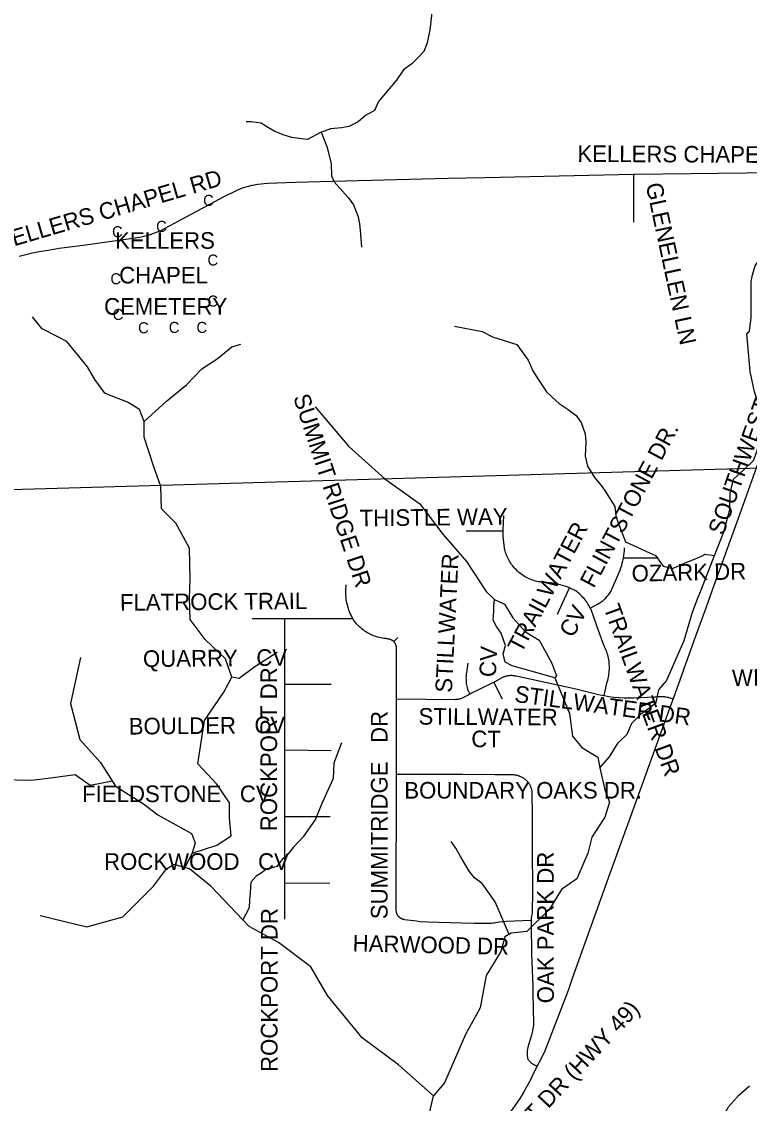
# Model space of a CAD drawing. Extents: x 1670563 to 1761545, y 515755 to 578944.
# Drawn here: x 1684631 to 1687923, y 530609 to 535500 of the extents above; entities that cross this region are included whole.
import ezdxf

# ---------------------------------------------------------------- set-up
doc = ezdxf.new("R2010")
doc.units = 0
for name, color, linetype in [('4_TwnRge', 7, 'Continuous'), ('CEMETERY', 7, 'Continuous'), ('Cross', 7, 'Continuous'), ('SHP_LINE', 7, 'Continuous'), ('STREETCL', 7, 'Continuous'), ('STRNAMES', 7, 'Continuous')]:
    doc.layers.add(name, color=color, linetype=linetype)

msp = doc.modelspace()

# ---------------------------------------------------------------- linework, layer by layer
at = {"layer": '4_TwnRge'}
msp.add_lwpolyline([(1677728, 533231.8), (1683031.7, 533346.7), (1683119.4, 533342.5), (1688238.5, 533490), (1688376.1, 533487.8), (1693684.6, 533590.9), (1698873.3, 533608.2), (1704126.3, 533645.6)], dxfattribs=at)
at = {"layer": 'SHP_LINE'}
for points in [[(1686501, 535615), (1686490, 535580), (1686486, 535528), (1686478, 535463), (1686465, 535405), (1686450, 535365), (1686421, 535334), (1686396, 535309), (1686359, 535282), (1686327, 535236), (1686246, 535139), (1686227, 535099), (1686187, 535076), (1686154, 535047), (1686112, 535026), (1686079, 535020), (1686029, 535016), (1685997, 535003), (1685987, 535001)], [(1685987, 535001), (1685924, 534968), (1685899, 534970), (1685853, 534976), (1685814, 534989), (1685774, 535005), (1685740, 535024), (1685715, 535041), (1685670, 535047), (1685647, 535047)], [(1685987, 535001), (1686012, 534936), (1686031, 534859), (1686033, 534803), (1686045, 534776), (1686108, 534705), (1686133, 534672), (1686154, 534617), (1686160, 534586), (1686162, 534557), (1686168, 534480)], [(1687766, 533086), (1687808, 533194), (1687834, 533294), (1687837, 533367), (1687851, 533432), (1687897, 533473), (1687942, 533516), (1687958, 533559), (1687975, 533638), (1687975, 533705), (1687969, 533759), (1687947, 533827), (1687926, 533919), (1687912, 534090), (1687923, 534101), (1687931, 534163), (1687931, 534176), (1687931, 534233), (1687931, 534266), (1687931, 534325), (1687937, 534355), (1687950, 534396), (1687958, 534409)], [(1685186, 533693), (1685164, 533747), (1685111, 533780), (1685037, 533808), (1685008, 533821), (1684963, 533882), (1684930, 533940), (1684877, 534005), (1684836, 534054), (1684795, 534075), (1684725, 534111), (1684705, 534136), (1684680, 534165)], [(1686589, 534123), (1686714, 534100), (1686762, 534075), (1686871, 534040), (1686922, 533969), (1686944, 533921), (1686970, 533880), (1687005, 533826), (1687031, 533803), (1687063, 533774), (1687104, 533746), (1687139, 533720), (1687162, 533688), (1687181, 533637), (1687184, 533599), (1687181, 533535), (1687191, 533490), (1687223, 533439), (1687255, 533401), (1687271, 533378), (1687315, 533308), (1687319, 533266), (1687328, 533238), (1687363, 533148), (1687472, 533099), (1687498, 533086), (1687533, 533038), (1687574, 533028), (1687594, 533035), (1687632, 533054), (1687683, 533073), (1687712, 533086), (1687722, 533092), (1687766, 533086)], [(1685186, 533693), (1685287, 533784), (1685377, 533858), (1685447, 533931), (1685516, 533976), (1685582, 534030), (1685623, 534042)], [(1685959, 533758), (1686112, 533579), (1686274, 533433), (1686433, 533320), (1686537, 533183), (1686644, 533060), (1686732, 532924), (1686771, 532888)], [(1685582, 532536), (1685553, 532619), (1685462, 532707), (1685394, 532797), (1685391, 532895), (1685394, 532979), (1685391, 533119), (1685329, 533232), (1685264, 533297), (1685261, 533398), (1685229, 533488), (1685186, 533621), (1685186, 533693)], [(1687246, 532127), (1687290, 532176), (1687329, 532239), (1687370, 532279), (1687392, 532328), (1687436, 532373), (1687473, 532400), (1687501, 532422), (1687514, 532479), (1687548, 532520), (1687628, 532702), (1687666, 532830), (1687692, 532898), (1687707, 532934), (1687766, 533086)], [(1686771, 532888), (1686816, 532867), (1686853, 532805), (1686910, 532742), (1686973, 532704), (1687028, 532603), (1687050, 532542), (1687043, 532534), (1686850, 532587), (1686818, 532604), (1686810, 532642), (1686820, 532679), (1686801, 532735), (1686780, 532766), (1686764, 532794), (1686767, 532836), (1686767, 532861), (1686771, 532888)], [(1685787, 532648), (1685686, 532583), (1685615, 532531), (1685582, 532536)], [(1684897, 532625), (1684852, 532417), (1684894, 532255), (1684988, 532151), (1685056, 532044), (1685183, 531963), (1685248, 531914), (1685400, 531830), (1685416, 531787), (1685403, 531741), (1685369, 531676)], [(1685403, 531741), (1685514, 531777), (1685579, 531819), (1685572, 531900), (1685572, 531968), (1685514, 532053), (1685429, 532144), (1685459, 532341), (1685546, 532468), (1685582, 532536)], [(1687043, 532534), (1687109, 532372), (1687123, 532270), (1687165, 532219), (1687237, 532175), (1687246, 532127)], [(1686078, 532239), (1686044, 532147), (1686040, 532079), (1685989, 531966), (1685960, 531894), (1685905, 531814), (1685887, 531795), (1685859, 531766), (1685830, 531729), (1685810, 531712), (1685786, 531680), (1685744, 531669), (1685734, 531665), (1685715, 531651), (1685692, 531636), (1685670, 531611), (1685667, 531596), (1685667, 531587), (1685665, 531561), (1685662, 531529), (1685661, 531493), (1685632, 531439)], [(1687246, 532127), (1687270, 532027), (1687290, 531971), (1687269, 531904), (1687211, 531813), (1687193, 531740), (1687143, 531624), (1687074, 531576), (1687019, 531487), (1686917, 531387), (1686846, 531379)], [(1685042, 532066), (1684942, 532046), (1684874, 532095), (1684774, 532082), (1684676, 532069), (1684540, 532072), (1684443, 532059), (1684355, 532053), (1684257, 531955), (1684173, 531897), (1684102, 531800)], [(1686836, 531373), (1686773, 531520), (1686714, 531604), (1686680, 531629), (1686655, 531659), (1686617, 531726), (1686596, 531764), (1686575, 531793)], [(1684715, 531459), (1684926, 531407), (1685089, 531453), (1685228, 531592), (1685287, 531670), (1685320, 531689)], [(1685632, 531439), (1685488, 531592), (1685391, 531670), (1685320, 531689)], [(1686495, 530643), (1686336, 530783), (1686171, 530906), (1686015, 531097), (1685940, 531227), (1685794, 531337), (1685661, 531409), (1685632, 531439)], [(1686846, 531379), (1686817, 531362), (1686799, 531296), (1686733, 531187), (1686706, 531041), (1686639, 530921), (1686544, 530703), (1686495, 530643)], [(1686476, 530565), (1686495, 530643)], [(1688266, 529793), (1687440, 530142), (1687363, 530202), (1687363, 530262), (1687401, 530294), (1687446, 530332), (1687455, 530395), (1687478, 530414), (1687573, 530455), (1687636, 530468), (1687712, 530468), (1687750, 530493), (1687788, 530531), (1687813, 530566), (1687829, 530594), (1687874, 530645), (1687924, 530689)]]:
    msp.add_lwpolyline(points, dxfattribs=at)
at = {"layer": 'STREETCL'}
for points in [[(1684619.7, 534440.2), (1684650.8, 534447.6), (1684681.1, 534454.3), (1684711.5, 534460.2), (1684752.2, 534467.6), (1684801.8, 534475.3), (1684873.6, 534484.6), (1684943.2, 534494.2), (1685166.7, 534526.4), (1685208.1, 534536), (1685234, 534545.7), (1685260.7, 534556), (1685544.2, 534707.6), (1685609.3, 534740.2), (1685630, 534748.3), (1685674.4, 534760.3), (1685700.3, 534765.4), (1685744, 534769.9), (1685869.8, 534775.1), (1686037.8, 534779.5), (1686560.8, 534792.1), (1686725.9, 534795.8), (1687398.8, 534810.5)], [(1687398.8, 534810.5), (1687405.4, 534810.6), (1687909.4, 534817.3), (1688089.3, 534821), (1688446, 534826.6)], [(1687398.8, 534810.5), (1687398.8, 534593.3)], [(1688443.6, 534819.6), (1688398.8, 534697.6), (1688346, 534561.1), (1688303.2, 534451.7), (1688196.4, 534149.1), (1688085.6, 533847.5), (1687978.7, 533549.9), (1687871.9, 533253.3), (1687762.2, 532951.2), (1687727.1, 532852.3), (1687671.8, 532700.8), (1687577.9, 532437.9)], [(1687109.5, 532940.2), (1687099.2, 532944.3), (1687088.7, 532948), (1687078.2, 532951.4), (1687067.5, 532954.4), (1687056.7, 532957), (1687045.8, 532959.2), (1687034.9, 532961.1), (1687023.9, 532962.6), (1687012.8, 532963.6), (1687001.8, 532964.4), (1686995.1, 532964.6), (1686988.4, 532965.2), (1686981.7, 532965.9), (1686975.1, 532966.9), (1686968.4, 532968.1), (1686961.9, 532969.5), (1686955.4, 532971.2), (1686948.9, 532973.1), (1686942.6, 532975.2), (1686936.3, 532977.5), (1686930, 532980), (1686923.9, 532982.8), (1686917.9, 532985.7), (1686912, 532988.9), (1686906.1, 532992.2), (1686900.4, 532995.8), (1686894.9, 532999.5), (1686889.4, 533003.4), (1686884.1, 533007.6), (1686879, 533011.9), (1686874, 533016.3), (1686869.1, 533021), (1686864.4, 533025.8), (1686859.9, 533030.7), (1686855.5, 533035.8), (1686851.4, 533041.1), (1686847.4, 533046.5), (1686843.6, 533052), (1686840, 533057.7), (1686836.6, 533063.5), (1686833.3, 533069.4), (1686830.3, 533075.4), (1686827.5, 533081.5), (1686824.9, 533087.7), (1686822.5, 533093.9), (1686820.4, 533100.3), (1686818.4, 533106.7), (1686815.8, 533120.1), (1686813.7, 533133.5), (1686811.9, 533147), (1686810.5, 533160.5), (1686809.6, 533174), (1686809, 533187.6), (1686808.9, 533201.2), (1686811.8, 533268)], [(1686641.5, 533197.7), (1686808.6, 533198.6)], [(1687353.3, 533074.1), (1687355.3, 533086), (1687356.8, 533097.9), (1687358, 533109.8), (1687358.7, 533121.8)], [(1687203.7, 532848.5), (1687239.3, 532867.9), (1687243.9, 532870.7), (1687248.5, 532873.6), (1687252.9, 532876.7), (1687257.2, 532879.9), (1687261.4, 532883.3), (1687265.5, 532886.8), (1687269.5, 532890.5), (1687273.3, 532894.3), (1687277, 532898.2), (1687280.6, 532902.3), (1687284, 532906.5), (1687287.3, 532910.8), (1687290.4, 532915.2), (1687293.4, 532919.7), (1687296.2, 532924.3), (1687298.9, 532929), (1687301.4, 532933.8), (1687338.6, 533019.7), (1687342.3, 533030.4), (1687345.6, 533041.2), (1687348.5, 533052.1), (1687351.1, 533063.1), (1687353.3, 533074.1)], [(1687506.7, 533075), (1687353.3, 533074.1)], [(1686129.1, 532802.2), (1686125.1, 532809.5), (1686121.4, 532816.9), (1686118, 532824.4), (1686114.8, 532832.1), (1686111.9, 532839.8), (1686109.3, 532847.6), (1686106.9, 532855.5), (1686104.8, 532863.5), (1686103, 532871.6), (1686101.4, 532879.7), (1686100.1, 532887.9), (1686099.1, 532896.1), (1686098.4, 532904.3), (1686098, 532912.6), (1686097.8, 532920.9), (1686097.9, 532929.1), (1686098.4, 532937.4), (1686099, 532945.6), (1686100, 532953.8)], [(1687054.8, 532821.6), (1687109.5, 532940.2)], [(1687203.7, 532848.5), (1687200.3, 532855), (1687196.7, 532861.5), (1687192.8, 532867.8), (1687188.8, 532873.9), (1687184.5, 532880), (1687180.1, 532885.8), (1687175.4, 532891.6), (1687170.6, 532897.1), (1687165.5, 532902.5), (1687160.3, 532907.7), (1687154.9, 532912.8), (1687149.4, 532917.6), (1687143.7, 532922.3), (1687137.8, 532926.8), (1687128.5, 532931.6), (1687119.1, 532936), (1687109.5, 532940.2)], [(1687265.9, 532452.8), (1687280.1, 532515.8), (1687282.2, 532522.7), (1687284, 532529.7), (1687285.7, 532536.7), (1687287, 532543.8), (1687288.1, 532551), (1687289, 532558.1), (1687289.7, 532565.3), (1687290, 532572.5), (1687290.2, 532579.8), (1687290.1, 532587), (1687289.7, 532594.2), (1687289.1, 532601.4), (1687288.3, 532608.6), (1687287.2, 532615.7), (1687285.9, 532622.8), (1687284.3, 532629.8), (1687282.5, 532636.8), (1687280.5, 532643.8), (1687278.2, 532650.6), (1687275.7, 532657.4), (1687272.9, 532664.1), (1687269.9, 532670.6), (1687266.7, 532677.1), (1687234.3, 532764), (1687215.2, 532820.8), (1687212.7, 532827.9), (1687209.9, 532834.9), (1687206.9, 532841.7), (1687203.7, 532848.5)], [(1685674.6, 532802.2), (1685822.6, 532802.2)], [(1685822.6, 532504.2), (1685822.6, 532802.2)], [(1685822.6, 532802.2), (1686129.1, 532802.2)], [(1686314.7, 532697.6), (1686313.6, 532698.7), (1686312.6, 532699.7), (1686311.5, 532700.7), (1686310.3, 532701.6), (1686307.7, 532702.9), (1686305, 532704.1), (1686302.3, 532705.2), (1686299.6, 532706.1), (1686296.8, 532707.1), (1686294, 532707.9), (1686291.1, 532708.6), (1686288.3, 532709.2), (1686285.4, 532709.7), (1686282.5, 532710.1), (1686279.6, 532710.5), (1686276.7, 532710.7), (1686269.9, 532711.5), (1686263.1, 532712.5), (1686256.4, 532713.8), (1686249.7, 532715.3), (1686243, 532717), (1686236.5, 532718.9), (1686230, 532721.1), (1686223.5, 532723.5), (1686217.2, 532726.1), (1686211, 532729), (1686204.8, 532732), (1686198.8, 532735.2), (1686192.9, 532738.7), (1686187.1, 532742.3), (1686181.4, 532746.2), (1686175.9, 532750.2), (1686170.5, 532754.5), (1686165.2, 532758.9), (1686160.1, 532763.4), (1686155.2, 532768.2), (1686150.4, 532773.1), (1686145.8, 532778.2), (1686141.4, 532783.4), (1686137.2, 532788.8), (1686133, 532795.5), (1686129.1, 532802.2)], [(1686333.6, 532715.9), (1686314.7, 532697.6)], [(1686327.2, 532437.8), (1686327.4, 532663.3), (1686327.4, 532664.9), (1686327.5, 532666.4), (1686327.4, 532668), (1686327.3, 532669.6), (1686327.2, 532671.1), (1686327, 532672.7), (1686326.7, 532674.2), (1686326.4, 532675.8), (1686326, 532677.3), (1686325.6, 532678.8), (1686325.1, 532680.3), (1686324.6, 532681.8), (1686324, 532683.3), (1686323.4, 532684.7), (1686322.8, 532686.1), (1686322, 532687.5), (1686321.3, 532688.9), (1686320.5, 532690.2), (1686319.6, 532691.5), (1686318.7, 532692.8), (1686317.8, 532694.1), (1686316.8, 532695.3), (1686315.8, 532696.5), (1686314.7, 532697.6)], [(1686649.5, 532599.8), (1686643.3, 532557.8), (1686642.5, 532551.6), (1686641.9, 532545.5), (1686641.5, 532539.3), (1686641.3, 532533.1), (1686641.4, 532526.9), (1686641.7, 532520.7), (1686642.1, 532514.5), (1686642.8, 532508.3), (1686643.7, 532502.2), (1686644.8, 532496.1), (1686646.1, 532490), (1686646.9, 532486.9), (1686647.8, 532483.8), (1686648.8, 532480.7), (1686649.9, 532477.7), (1686651.1, 532474.7), (1686652.4, 532471.7), (1686653.8, 532468.8), (1686655.3, 532465.9), (1686656.9, 532463.1), (1686658.5, 532460.4)], [(1685822.6, 532504.2), (1686030.9, 532504.2)], [(1685822.6, 532205.7), (1685822.6, 532365.1), (1685822.6, 532504.2)], [(1686658.5, 532460.4), (1686767, 532514)], [(1686767, 532514), (1686792.7, 532526.7), (1686795.1, 532528.5), (1686797.6, 532530.2), (1686800.1, 532531.8), (1686802.6, 532533.3), (1686805.2, 532534.8), (1686807.9, 532536.1), (1686810.6, 532537.3), (1686813.3, 532538.5), (1686816.1, 532539.6), (1686818.9, 532540.5), (1686821.7, 532541.4), (1686824.6, 532542.2), (1686827.5, 532542.9), (1686830.4, 532543.4), (1686833.3, 532543.9), (1686836.3, 532544.3), (1686839.2, 532544.6), (1686842.2, 532544.8), (1686845.2, 532544.8), (1686848.1, 532544.8), (1686851.1, 532544.7), (1686854.1, 532544.5), (1686857, 532544.1), (1686860, 532543.7), (1686862.9, 532543.2), (1686865.8, 532542.6), (1686868.7, 532541.8), (1687131.8, 532485), (1687229.2, 532460.4), (1687247.5, 532456.4), (1687265.9, 532452.8)], [(1686806.7, 532437.2), (1686767, 532514)], [(1686327.2, 532437.8), (1686588.8, 532436.1), (1686592.2, 532436.2), (1686595.6, 532436.3), (1686598.9, 532436.6), (1686602.3, 532437), (1686605.7, 532437.4), (1686609, 532438), (1686612.3, 532438.8), (1686615.6, 532439.6), (1686618.8, 532440.5), (1686622.1, 532441.6), (1686625.3, 532442.7), (1686628.4, 532444), (1686631.5, 532445.3), (1686634.6, 532446.8), (1686637.6, 532448.4), (1686640.5, 532450.1), (1686643.4, 532451.8), (1686646.2, 532453.7), (1686649, 532455.6), (1686658.5, 532460.4)], [(1687265.9, 532452.8), (1687288.1, 532449.3), (1687310.4, 532446.5), (1687332.7, 532444.4), (1687355.1, 532443), (1687377.6, 532442.4), (1687400.1, 532442.5), (1687494.4, 532447.3), (1687499.4, 532448.1), (1687504.4, 532448.8), (1687509.4, 532449.2), (1687514.4, 532449.5), (1687519.4, 532449.6), (1687524.4, 532449.6), (1687529.4, 532449.3), (1687534.4, 532448.9), (1687539.4, 532448.4), (1687544.3, 532447.6), (1687549.2, 532446.7), (1687554.1, 532445.7), (1687559, 532444.4), (1687563.8, 532443.1), (1687568.6, 532441.5), (1687573.3, 532439.8), (1687577.9, 532437.9)], [(1687577.9, 532437.9), (1687562.6, 532395), (1687422.2, 532006.5), (1687291.4, 531649.4), (1687207.9, 531414.2), (1687121.2, 531173.5), (1687102.8, 531119.8), (1686996.9, 530842.9), (1686945.6, 530742.8), (1686932.4, 530715.5), (1686918.3, 530688.7), (1686903.3, 530662.3), (1686887.5, 530636.5), (1686870.9, 530611.2), (1686853.4, 530586.4), (1686835.1, 530562.2), (1686816.1, 530538.7), (1686796.3, 530515.7), (1686735.9, 530448.1), (1686509.6, 530205), (1686326.6, 530009.9), (1686116.4, 529786.8), (1685986.2, 529648.2)], [(1686327, 532097.9), (1686327.2, 532437.8)], [(1686030.9, 532203.8), (1685822.6, 532205.7)], [(1685822.6, 531905.4), (1685822.6, 532037), (1685822.6, 532205.7)], [(1686337.5, 531453.2), (1686336.5, 531454.3), (1686335.6, 531455.4), (1686334.7, 531456.6), (1686333.8, 531457.7), (1686333, 531459), (1686332.2, 531460.2), (1686331.5, 531461.4), (1686330.8, 531462.7), (1686330.1, 531464), (1686329.5, 531465.4), (1686329, 531466.7), (1686328.4, 531468.1), (1686328, 531469.5), (1686327.5, 531470.9), (1686327.2, 531472.3), (1686326.8, 531473.7), (1686326.6, 531475.1), (1686326.3, 531476.6), (1686326.2, 531478), (1686326, 531479.5), (1686325.9, 531480.9), (1686325.9, 531482.4), (1686325.9, 531483.8), (1686326, 531485.3), (1686327, 532096.6), (1686327, 532097.9)], [(1686327, 532097.9), (1686625.9, 532097.8), (1686771.9, 532096.4), (1686840.7, 532095.7), (1686844, 532095.9), (1686847.2, 532096), (1686850.5, 532096), (1686853.8, 532095.9), (1686857, 532095.7), (1686860.3, 532095.3), (1686863.5, 532094.8), (1686866.7, 532094.3), (1686869.9, 532093.6), (1686873.1, 532092.8), (1686876.3, 532091.9), (1686879.4, 532090.9), (1686882.4, 532089.8), (1686885.5, 532088.6), (1686888.5, 532087.2), (1686891.4, 532085.8), (1686894.3, 532084.3), (1686897.2, 532082.7), (1686899.9, 532080.9), (1686902.7, 532079.1), (1686905.3, 532077.2), (1686907.9, 532075.2), (1686910.4, 532073.1), (1686912.9, 532071), (1686915.3, 532068.7), (1686917.6, 532066.4), (1686919.8, 532064)], [(1686919.8, 532064), (1686921.6, 532061.8), (1686923.3, 532059.6), (1686925, 532057.3), (1686926.6, 532054.9), (1686928.1, 532052.5), (1686929.5, 532050.1), (1686930.8, 532047.6), (1686932, 532045), (1686933.2, 532042.5), (1686934.2, 532039.8), (1686935.2, 532037.2), (1686936.1, 532034.5), (1686936.8, 532031.8), (1686937.5, 532029), (1686938.1, 532026.2), (1686938.6, 532023.5), (1686939, 532020.7), (1686939.3, 532017.8), (1686939.5, 532015), (1686939.6, 532012.2), (1686939.6, 532009.4), (1686939.5, 532006.5), (1686939.3, 532003.7), (1686940, 531918.1), (1686940.8, 531768.4), (1686942.8, 531566.6), (1686941.3, 531471.7), (1686936.6, 531445.4), (1686936.2, 531440.6), (1686935.9, 531435.9)], [(1686027.1, 531905.4), (1685822.6, 531905.4)], [(1685822.6, 531605), (1685822.6, 531710.9), (1685822.6, 531905.4)], [(1686026.2, 531604.1), (1685822.6, 531605)], [(1685822.6, 531441.7), (1685822.6, 531605)], [(1686935.9, 531435.9), (1686860.2, 531433.4), (1686823.8, 531431.5), (1686807.7, 531430.1), (1686791.7, 531428.2), (1686775.8, 531425.7), (1686768.9, 531424.6), (1686762.1, 531423.7), (1686755.2, 531423.1), (1686748.3, 531422.8), (1686741.4, 531422.6), (1686734.5, 531422.8), (1686678.1, 531422.2), (1686569.7, 531425.7), (1686467, 531428.4), (1686434.4, 531430.9), (1686417.6, 531433.8), (1686362.8, 531439.9), (1686361.4, 531440.2), (1686360, 531440.5), (1686358.5, 531440.8), (1686357.1, 531441.2), (1686355.7, 531441.6), (1686354.4, 531442.1), (1686353, 531442.6), (1686351.7, 531443.2), (1686350.3, 531443.8), (1686349, 531444.4), (1686347.7, 531445.1), (1686346.5, 531445.9), (1686345.3, 531446.6), (1686344.1, 531447.5), (1686342.9, 531448.3), (1686341.7, 531449.2), (1686340.6, 531450.2), (1686339.6, 531451.2), (1686338.5, 531452.2), (1686337.5, 531453.2)], [(1686935.9, 531435.9), (1686935.7, 531427.5), (1686935.7, 531419.1), (1686938, 531286.2), (1686943.4, 531138.1), (1686945.7, 531008.2), (1686946.4, 531000.6), (1686946.9, 530992.9), (1686947.1, 530985.3), (1686947, 530977.6), (1686946.7, 530969.9), (1686946.1, 530962.3), (1686945.3, 530954.7), (1686944.2, 530947.1), (1686942.9, 530939.5), (1686941.3, 530932), (1686939.5, 530924.5), (1686937.4, 530917.2), (1686921.5, 530863.3), (1686919.7, 530854.9), (1686919.1, 530851.8), (1686918.6, 530848.6), (1686918.2, 530845.3), (1686917.9, 530842.1), (1686917.7, 530838.9), (1686917.7, 530835.6), (1686917.7, 530832.4), (1686917.8, 530829.2), (1686918.1, 530825.9), (1686918.4, 530822.7), (1686918.9, 530819.5), (1686919.5, 530816.3), (1686920.1, 530813.1), (1686920.9, 530810), (1686922.3, 530807.9), (1686923.7, 530805.9), (1686925.2, 530804), (1686926.8, 530802.1), (1686928.5, 530800.2), (1686930.2, 530798.4), (1686931.9, 530796.7), (1686933.8, 530795), (1686935.6, 530793.4), (1686937.6, 530791.8), (1686939.5, 530790.3), (1686941.6, 530788.9), (1686943.6, 530787.6), (1686945.8, 530786.3), (1686947.9, 530785.1), (1686950.1, 530784), (1686952.4, 530782.9), (1686954.6, 530781.9), (1686957, 530781), (1686959.3, 530780.2), (1686961.6, 530779.5), (1686964, 530778.8)]]:
    msp.add_lwpolyline(points, dxfattribs=at)

# ---------------------------------------------------------------- texts
at = {"layer": 'CEMETERY'}
for s, p in [('KELLERS', (1685054, 534473.2)), ('CHAPEL', (1685072.7, 534316.4)), ('CEMETERY', (1685004.2, 534175.1))]:
    msp.add_text(s, height=75, dxfattribs=at).set_placement(p)
at = {"layer": 'Cross'}
for p in [(1685452.4, 534667.1), (1685040.5, 534525.4), (1685239.7, 534549.5), (1685472.1, 534397.3), (1685033, 534312.8), (1685472.1, 534211.8), (1685043.5, 534151.5), (1685158.2, 534091.2), (1685297, 534092.7), (1685422.3, 534092.7)]:
    msp.add_text('C', height=50, dxfattribs=at).set_placement(p)
at = {"layer": 'STRNAMES'}
for s, rotation, p in [('KELLERS CHAPEL RD', 359.6764, (1687145, 534866.3)), ('KELLERS CHAPEL RD', 16.3437, (1684533.1, 534465.2)), ('GLENELLEN LN', 282.143, (1687453.8, 534763.3)), ('SOUTHWEST DR. (HWY. #49)', 70.4115, (1687805.3, 533174.2)), ('SUMMIT RIDGE DR', 288.2558, (1685858.9, 533802.6)), ('FLINTSTONE DR.', 62.0319, (1687219.4, 532935.1)), ('THISTLE WAY', 0.6487, (1686160.9, 533218.2)), ('TRAILWATER ', 62.0319, (1686891.9, 532640.9)), ('STILLWATER ', 87.1755, (1686577.4, 532464.8)), ('OZARK DR', 1.1678, (1687391.2, 532968.1)), ('FLATROCK TRAIL', 0.542, (1685076.6, 532836.6)), ('CV', 62.0319, (1687125.5, 532710.9)), ('TRAILWATER DR', 290.0168, (1687262.7, 532850.6)), ('QUARRY   CV', 0.542, (1685180.6, 532582.3)), ('CV', 87.1755, (1686776.2, 532535.1)), ('ROCKPORT DR', 90, (1685786.8, 531840)), ('WINTERHAVEN ST', 0.9952, (1687845, 532495.7)), ('STILLWATER DR', 352.3279, (1686857.6, 532425.1)), ('BOULDER   CV', 0.542, (1685116.3, 532276.9)), ('SUMMITRIDGE   DR', 90, (1686286.5, 531442.1)), ('STILLWATER', 359.6587, (1686426.4, 532321.9)), ('CT', 359.6587, (1686665.1, 532220)), ('OAK PARK DR', 90.0747, (1687038.8, 531061.9)), ('ROCKPORT DR', 90, (1685788.8, 530751.4)), ('HARWOOD DR', 358.7527, (1686128.1, 531296.4)), ('SOUTHWEST DR (HWY 49)', 46.8908, (1686556.5, 530095.1))]:
    msp.add_text(s, height=75, rotation=rotation, dxfattribs=at).set_placement(p)
for s, p in [('BOUNDARY OAKS DR.', (1686362.3, 531987.5)), ('FIELDSTONE   CV', (1684905.3, 531971.5)), ('ROCKWOOD   CV', (1685004.4, 531665.3))]:
    msp.add_text(s, height=75, dxfattribs=at).set_placement(p)

doc.saveas('drawing.dxf')
